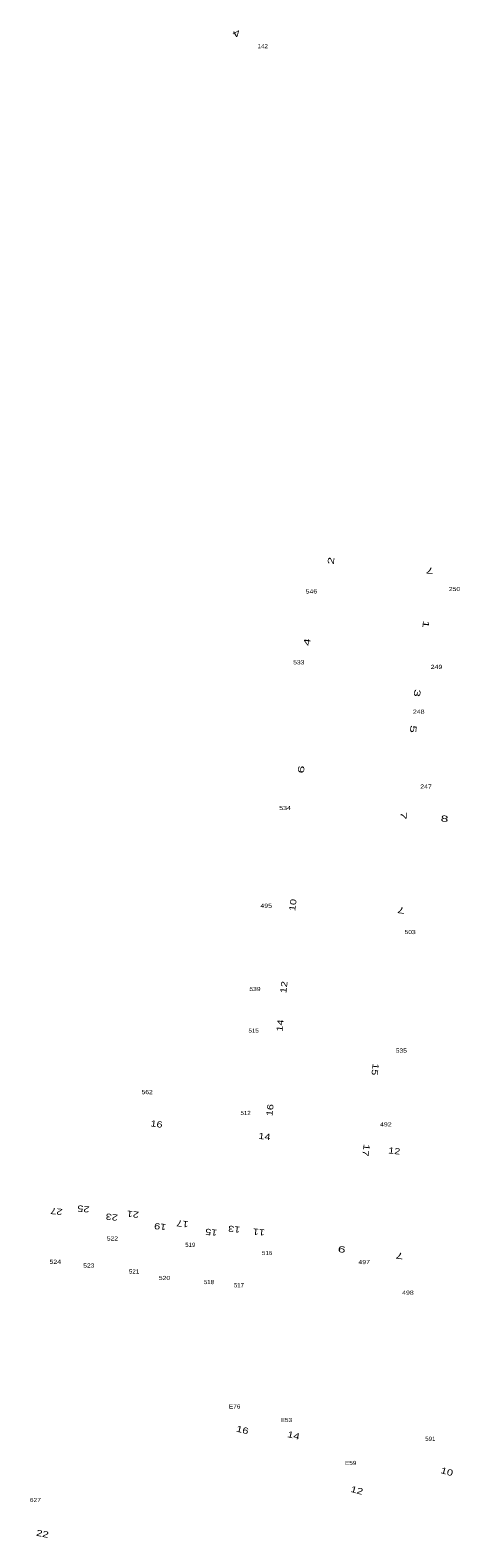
# Model space of a CAD drawing. Extents: x -828673 to -815583, y -1077737 to -1063807.
# Drawn here: x -821345.7 to -821242.5, y -1072946.3 to -1072583.8 of the extents above; entities that cross this region are included whole.
import ezdxf
from ezdxf.enums import TextEntityAlignment as Align

# ---------------------------------------------------------------- set-up
doc = ezdxf.new("R2010")
doc.units = 0
doc.header["$LTSCALE"] = 0.4
doc.layers.add('1', color=7, linetype='Continuous')
doc.layers.add('2', color=7, linetype='Continuous')

msp = doc.modelspace()

# ---------------------------------------------------------------- texts
at = {"layer": '1'}
for s, width, p in [('142', 1.1, (-821289.832, -1072588.135)), ('546', 1.25, (-821278.145, -1072719.223)), ('250', 1.2, (-821243.74, -1072718.642)), ('533', 1.2, (-821281.173, -1072736.272)), ('249', 1.25, (-821248.068, -1072737.362)), ('248', 1.25, (-821252.341, -1072748.133)), ('247', 1.25, (-821250.589, -1072766.136)), ('534', 1.25, (-821284.482, -1072771.292)), ('495', 1.25, (-821289.005, -1072794.789)), ('503', 1.2, (-821254.419, -1072801.114)), ('539', 1.2, (-821291.71, -1072814.816)), ('515', 1.1, (-821292.032, -1072824.812)), ('535', 1.2, (-821256.53, -1072829.613)), ('562', 1.2, (-821317.62, -1072839.597)), ('512', 1.1, (-821293.97, -1072844.608)), ('492', 1.25, (-821260.252, -1072847.355)), ('522', 1.2, (-821325.972, -1072874.782)), ('519', 1.1, (-821307.249, -1072876.307)), ('524', 1.25, (-821339.704, -1072880.394)), ('516', 1.1, (-821288.781, -1072878.266)), ('497', 1.25, (-821265.449, -1072880.457)), ('523', 1.2, (-821331.651, -1072881.289)), ('521', 1.1, (-821320.772, -1072882.723)), ('520', 1.2, (-821313.443, -1072884.279)), ('518', 1.1, (-821302.777, -1072885.264)), ('517', 1.1, (-821295.568, -1072886.023)), ('498', 1.25, (-821254.939, -1072887.813)), ('E76', 1.15, (-821296.594, -1072915.17)), ('E53', 1.15, (-821284.169, -1072918.43)), ('591', 1.1, (-821249.557, -1072922.944)), ('E59', 1.15, (-821268.706, -1072928.752)), ('627', 1.2, (-821344.49, -1072937.66))]:
    msp.add_text(s, height=1, dxfattribs=dict(at, width=width)).set_placement(p, align=Align.CENTER)
at = {"layer": '2'}
for s, rotation, width, p in [('4', 211.132, 1.7, (-821296.5222, -1072583.946)), ('2', 84.729, 1.6, (-821272.6951, -1072711.4069)), ('7', 173.869, 1.65, (-821249.5864, -1072712.9793)), ('1', 263.928, 1.6, (-821251.3727, -1072726.5252)), ('4', 82.195, 1.65, (-821278.4495, -1072731.0014)), ('3', 263.132, 1.65, (-821253.4335, -1072743.0743)), ('5', 263.168, 1.65, (-821254.3909, -1072751.7363)), ('6', 83.324, 1.65, (-821279.8696, -1072761.6167)), ('7', 263.513, 1.65, (-821256.7173, -1072772.5328)), ('8', 353.66, 1.65, (-821246.2218, -1072774.104)), ('10', 83.21, 1.3, (-821281.8781, -1072794.1977)), ('7', 173.784, 1.65, (-821256.5093, -1072794.642)), ('12', 83.75, 1.3, (-821284.0221, -1072813.9427)), ('14', 83.464, 1.3, (-821284.9476, -1072823.1699)), ('15', 263.808, 1.3, (-821263.5494, -1072833.5446)), ('16', 83.79, 1.3, (-821287.3741, -1072843.4926)), ('16', 352.658, 1.3, (-821315.4543, -1072847.5003)), ('14', 353.721, 1.3, (-821289.5025, -1072850.4817)), ('17', 263.172, 1.3, (-821265.7349, -1072852.9833)), ('12', 353.725, 1.3, (-821258.2965, -1072853.9756)), ('27', 173.853, 1.3, (-821339.3487, -1072867.0468)), ('25', 173.8, 1.3, (-821332.8675, -1072866.4324)), ('23', 173.702, 1.3, (-821326.0457, -1072868.4088)), ('21', 173.781, 1.3, (-821320.9708, -1072867.7219)), ('19', 173.771, 1.3, (-821314.4056, -1072870.6896)), ('17', 173.943, 1.3, (-821309.0569, -1072870.0081)), ('15', 173.784, 1.3, (-821302.1323, -1072872.056)), ('13', 173.781, 1.3, (-821296.6178, -1072871.3239)), ('11', 173.928, 1.3, (-821290.6972, -1072872.0056)), ('9', 172.945, 1.65, (-821270.7489, -1072876.1605)), ('7', 173.494, 1.65, (-821256.869, -1072877.7203)), ('16', 346.527, 1.35, (-821294.8937, -1072921.0249)), ('14', 346.759, 1.35, (-821282.6033, -1072922.349)), ('10', 344.146, 1.35, (-821245.7649, -1072931.0541)), ('12', 345.211, 1.35, (-821267.3989, -1072935.5578)), ('22', 349.114, 1.35, (-821342.9271, -1072946.0011))]:
    msp.add_text(s, height=1.5, rotation=rotation, dxfattribs=dict(at, width=width)).set_placement(p, align=Align.CENTER)

doc.saveas('drawing.dxf')
